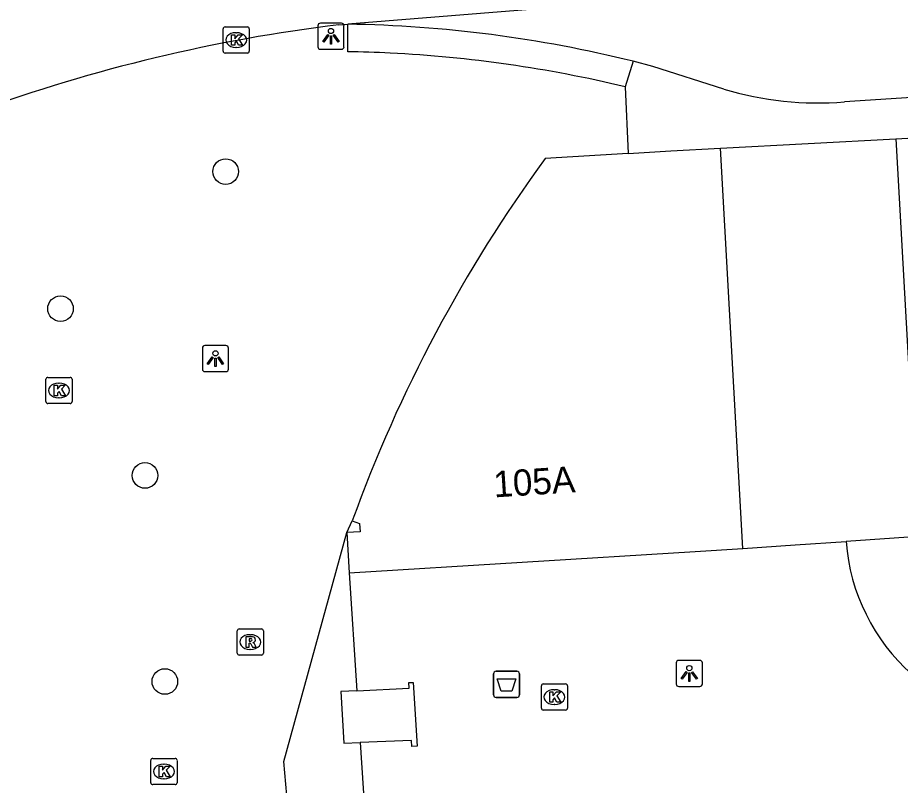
# Model space of a CAD drawing. Extents: x 159689 to 160786, y 387323 to 388339.
# Drawn here: x 160232.81 to 160266.51, y 387796.36 to 387825.64 of the extents above; entities that cross this region are included whole.
import ezdxf

# ---------------------------------------------------------------- set-up
doc = ezdxf.new("R2010")
doc.units = 0
for name, color, linetype in [('IMGEO_Afvalbak', 7, 'Continuous'), ('IMGEO_Boom', 7, 'Continuous'), ('IMGEO_Kolk', 7, 'Continuous'), ('IMGEO_Lichtpunt', 7, 'Continuous'), ('IMGEO_Pand', 7, 'Continuous'), ('IMGEO_Pand_nummerreeks', 7, 'Continuous'), ('IMGEO_Rijbaan_lokaal_open', 7, 'Continuous'), ('IMGEO_Rioolput', 7, 'Continuous'), ('IMGEO_Voetpad_open', 7, 'Continuous')]:
    doc.layers.add(name, color=color, linetype=linetype)

msp = doc.modelspace()

# ---------------------------------------------------------------- linework, layer by layer
at = {"layer": 'IMGEO_Afvalbak'}
for p, q in [((160250.976, 387799.808), (160250.976, 387800.608)), ((160250.976, 387800.608), (160250.976, 387799.808)), ((160251.076, 387800.708), (160251.866, 387800.708)), ((160251.866, 387800.708), (160251.076, 387800.708)), ((160251.966, 387800.608), (160251.966, 387799.808)), ((160251.966, 387799.808), (160251.966, 387800.608)), ((160251.866, 387799.708), (160251.076, 387799.708)), ((160251.076, 387799.708), (160251.866, 387799.708))]:
    msp.add_line(p, q, dxfattribs=at)
msp.add_lwpolyline([(160251.119, 387800.422), (160251.823, 387800.422), (160251.674, 387799.952), (160251.268, 387799.952), (160251.119, 387800.422)], dxfattribs=at)
for centre, start, end in [((160251.076, 387800.608), 90, 180), ((160251.076, 387800.608), 90, 180), ((160251.866, 387800.608), 0, 90), ((160251.866, 387800.608), 360, 90), ((160251.076, 387799.808), 180, 270), ((160251.076, 387799.808), 180, 270), ((160251.866, 387799.808), 270, 0), ((160251.866, 387799.808), 270, 0)]:
    msp.add_arc(centre, 0.1, start, end, dxfattribs=at)
at = {"layer": 'IMGEO_Boom'}
for centre in [(160240.754, 387819.771), (160234.448, 387814.541), (160237.673, 387808.179), (160238.431, 387800.318)]:
    msp.add_circle(centre, 0.489, dxfattribs=at)
at = {"layer": 'IMGEO_Kolk'}
for p, q in [((160240.654, 387824.364), (160240.654, 387825.216)), ((160240.729, 387825.29), (160241.581, 387825.29)), ((160241.142, 387825.07), (160241.167, 387825.07)), ((160241.655, 387825.216), (160241.655, 387824.364)), ((160241.165, 387824.51), (160241.14, 387824.51)), ((160241.581, 387824.29), (160240.729, 387824.29)), ((160233.963, 387811.921), (160234.815, 387811.921)), ((160233.888, 387810.995), (160233.888, 387811.847)), ((160234.376, 387811.701), (160234.401, 387811.701)), ((160234.889, 387811.847), (160234.889, 387810.995)), ((160234.815, 387810.921), (160233.963, 387810.921)), ((160234.399, 387811.141), (160234.374, 387811.141)), ((160252.802, 387799.3), (160252.802, 387800.152)), ((160252.877, 387800.226), (160253.729, 387800.226)), ((160253.803, 387800.152), (160253.803, 387799.3)), ((160253.29, 387800.006), (160253.315, 387800.006)), ((160253.313, 387799.446), (160253.288, 387799.446)), ((160253.729, 387799.226), (160252.877, 387799.226)), ((160237.895, 387796.459), (160237.895, 387797.311)), ((160237.97, 387797.385), (160238.822, 387797.385)), ((160238.383, 387797.165), (160238.408, 387797.165)), ((160238.896, 387797.311), (160238.896, 387796.459)), ((160238.822, 387796.385), (160237.97, 387796.385)), ((160238.406, 387796.605), (160238.381, 387796.605))]:
    msp.add_line(p, q, dxfattribs=at)
for points in [[(160240.654, 387824.364), (160240.654, 387825.216)], [(160240.729, 387825.29), (160241.581, 387825.29)], [(160241.655, 387825.216), (160241.655, 387824.364)], [(160240.975, 387824.99), (160241.098, 387824.99), (160241.098, 387824.839), (160241.228, 387824.99), (160241.392, 387824.99), (160241.246, 387824.839), (160241.399, 387824.59), (160241.247, 387824.59), (160241.162, 387824.754), (160241.098, 387824.687), (160241.098, 387824.59), (160240.975, 387824.59), (160240.975, 387824.99)], [(160241.581, 387824.29), (160240.729, 387824.29)], [(160233.963, 387811.921), (160234.815, 387811.921)], [(160233.888, 387810.995), (160233.888, 387811.847)], [(160234.209, 387811.621), (160234.332, 387811.621), (160234.332, 387811.47), (160234.462, 387811.621), (160234.626, 387811.621), (160234.48, 387811.47), (160234.633, 387811.221), (160234.481, 387811.221), (160234.396, 387811.385), (160234.332, 387811.318), (160234.332, 387811.221), (160234.209, 387811.221), (160234.209, 387811.621)], [(160234.889, 387811.847), (160234.889, 387810.995)], [(160234.815, 387810.921), (160233.963, 387810.921)], [(160252.802, 387799.3), (160252.802, 387800.152)], [(160252.877, 387800.226), (160253.729, 387800.226)], [(160253.803, 387800.152), (160253.803, 387799.3)], [(160253.123, 387799.926), (160253.246, 387799.926), (160253.246, 387799.775), (160253.376, 387799.926), (160253.54, 387799.926), (160253.394, 387799.775), (160253.547, 387799.526), (160253.395, 387799.526), (160253.31, 387799.69), (160253.246, 387799.623), (160253.246, 387799.526), (160253.123, 387799.526), (160253.123, 387799.926)], [(160253.729, 387799.226), (160252.877, 387799.226)], [(160237.895, 387796.459), (160237.895, 387797.311)], [(160237.97, 387797.385), (160238.822, 387797.385)], [(160238.216, 387797.085), (160238.339, 387797.085), (160238.339, 387796.934), (160238.469, 387797.085), (160238.633, 387797.085), (160238.487, 387796.934), (160238.64, 387796.685), (160238.488, 387796.685), (160238.403, 387796.849), (160238.339, 387796.782), (160238.339, 387796.685), (160238.216, 387796.685), (160238.216, 387797.085)], [(160238.896, 387797.311), (160238.896, 387796.459)], [(160238.822, 387796.385), (160237.97, 387796.385)]]:
    msp.add_lwpolyline(points, dxfattribs=at)
for centre, start, end in [((160240.731, 387825.214), 91.552, 178.448), ((160240.731, 387825.214), 91.552, 178.448), ((160241.579, 387825.214), 1.552, 88.448), ((160241.579, 387825.214), 1.552, 88.448), ((160240.731, 387824.366), 181.552, 268.448), ((160240.731, 387824.366), 181.552, 268.448), ((160241.579, 387824.366), 271.552, 358.448), ((160241.579, 387824.366), 271.552, 358.448), ((160233.965, 387811.845), 91.552, 178.448), ((160233.965, 387811.845), 91.552, 178.448), ((160234.813, 387811.845), 1.552, 88.448), ((160234.813, 387811.845), 1.552, 88.448), ((160233.965, 387810.997), 181.552, 268.448), ((160233.965, 387810.997), 181.552, 268.448), ((160234.813, 387810.997), 271.552, 358.448), ((160234.813, 387810.997), 271.552, 358.448), ((160252.879, 387800.15), 91.552, 178.448), ((160252.879, 387800.15), 91.552, 178.448), ((160253.727, 387800.15), 1.552, 88.448), ((160253.727, 387800.15), 1.552, 88.448), ((160252.879, 387799.302), 181.552, 268.448), ((160252.879, 387799.302), 181.552, 268.448), ((160253.727, 387799.302), 271.552, 358.448), ((160253.727, 387799.302), 271.552, 358.448), ((160237.972, 387797.309), 91.552, 178.448), ((160237.972, 387797.309), 91.552, 178.448), ((160238.82, 387797.309), 1.552, 88.448), ((160238.82, 387797.309), 1.552, 88.448), ((160237.972, 387796.461), 181.552, 268.448), ((160237.972, 387796.461), 181.552, 268.448), ((160238.82, 387796.461), 271.552, 358.448), ((160238.82, 387796.461), 271.552, 358.448)]:
    msp.add_arc(centre, 0.0765, start, end, dxfattribs=at)
for centre, major_axis, ratio, start_param, end_param in [((160241.141, 387824.79), (-0.387, 0.002), 0.722429, 4.712389, 7.853982), ((160241.166, 387824.79), (-0.39, 0.002), 0.717154, 1.570796, 4.712389), ((160234.375, 387811.421), (-0.387, 0.002), 0.722429, 4.712389, 7.853982), ((160234.4, 387811.421), (-0.39, 0.002), 0.717154, 1.570796, 4.712389), ((160253.289, 387799.726), (-0.387, 0.002), 0.722429, 4.712389, 7.853982), ((160253.314, 387799.726), (-0.39, 0.002), 0.717154, 1.570796, 4.712389), ((160238.382, 387796.885), (-0.387, 0.002), 0.722429, 4.712389, 7.853982), ((160238.407, 387796.885), (-0.39, 0.002), 0.717154, 1.570796, 4.712389)]:
    msp.add_ellipse(centre, major_axis=major_axis, ratio=ratio, start_param=start_param, end_param=end_param, dxfattribs=at)
at = {"layer": 'IMGEO_Lichtpunt'}
for p, q in [((160245.175, 387825.432), (160244.367, 387825.432)), ((160245.175, 387825.432), (160244.367, 387825.432)), ((160244.273, 387825.337), (160244.273, 387824.53)), ((160244.273, 387825.337), (160244.273, 387824.53)), ((160245.269, 387824.53), (160245.269, 387825.337)), ((160245.269, 387824.53), (160245.269, 387825.337)), ((160244.367, 387824.436), (160245.175, 387824.436)), ((160244.367, 387824.436), (160245.175, 387824.436)), ((160239.863, 387813.04), (160239.863, 387812.233)), ((160239.863, 387813.04), (160239.863, 387812.233)), ((160240.765, 387813.135), (160239.957, 387813.135)), ((160240.765, 387813.135), (160239.957, 387813.135)), ((160240.859, 387812.233), (160240.859, 387813.04)), ((160240.859, 387812.233), (160240.859, 387813.04)), ((160239.957, 387812.139), (160240.765, 387812.139)), ((160239.957, 387812.139), (160240.765, 387812.139)), ((160258.854, 387801.125), (160258.046, 387801.125)), ((160258.854, 387801.125), (160258.046, 387801.125)), ((160257.952, 387801.03), (160257.952, 387800.223)), ((160257.952, 387801.03), (160257.952, 387800.223)), ((160258.948, 387800.223), (160258.948, 387801.03)), ((160258.948, 387800.223), (160258.948, 387801.03)), ((160258.046, 387800.129), (160258.854, 387800.129)), ((160258.046, 387800.129), (160258.854, 387800.129))]:
    msp.add_line(p, q, dxfattribs=at)
for points in [[(160244.647, 387825.001), (160244.686, 387824.973), (160244.498, 387824.711), (160244.46, 387824.738), (160244.647, 387825.001)], [(160244.749, 387824.953), (160244.796, 387824.953), (160244.796, 387824.631), (160244.749, 387824.631), (160244.749, 387824.953)], [(160244.859, 387824.973), (160244.897, 387825), (160245.084, 387824.738), (160245.045, 387824.71), (160244.859, 387824.973)], [(160240.237, 387812.704), (160240.276, 387812.676), (160240.088, 387812.414), (160240.05, 387812.441), (160240.237, 387812.704)], [(160240.339, 387812.656), (160240.386, 387812.656), (160240.386, 387812.334), (160240.339, 387812.334), (160240.339, 387812.656)], [(160240.449, 387812.676), (160240.487, 387812.703), (160240.674, 387812.441), (160240.635, 387812.413), (160240.449, 387812.676)], [(160258.326, 387800.694), (160258.365, 387800.666), (160258.177, 387800.404), (160258.139, 387800.431), (160258.326, 387800.694)], [(160258.428, 387800.646), (160258.475, 387800.646), (160258.475, 387800.324), (160258.428, 387800.324), (160258.428, 387800.646)], [(160258.538, 387800.666), (160258.576, 387800.693), (160258.763, 387800.431), (160258.724, 387800.403), (160258.538, 387800.666)]]:
    msp.add_lwpolyline(points, dxfattribs=at)
for centre in [(160244.772, 387825.135), (160240.362, 387812.838), (160258.451, 387800.828)]:
    msp.add_circle(centre, 0.0994, dxfattribs=at)
for centre, start, end in [((160244.367, 387825.337), 90, 180), ((160244.367, 387825.337), 90, 180), ((160245.175, 387825.337), 0, 90), ((160245.175, 387825.337), 0, 90), ((160244.367, 387824.53), 180, 270), ((160244.367, 387824.53), 180, 270), ((160245.175, 387824.53), 270, 0), ((160245.175, 387824.53), 270, 360), ((160239.957, 387813.04), 90, 180), ((160239.957, 387813.04), 90, 180), ((160240.765, 387813.04), 0, 90), ((160240.765, 387813.04), 0, 90), ((160239.957, 387812.233), 180, 270), ((160239.957, 387812.233), 180, 270), ((160240.765, 387812.233), 270, 0), ((160240.765, 387812.233), 270, 360), ((160258.046, 387801.03), 90, 180), ((160258.046, 387801.03), 90, 180), ((160258.854, 387801.03), 0, 90), ((160258.854, 387801.03), 0, 90), ((160258.046, 387800.223), 180, 270), ((160258.046, 387800.223), 180, 270), ((160258.854, 387800.223), 270, 0), ((160258.854, 387800.223), 270, 360)]:
    msp.add_arc(centre, 0.0946, start, end, dxfattribs=at)
at = {"layer": 'IMGEO_Pand'}
for points in [[(160266.337, 387821.024), (160273.033, 387821.388), (160273.123, 387820.044), (160312.863, 387822.702)], [(160259.64, 387820.661), (160266.337, 387821.024)], [(160266.337, 387821.024), (160267.186, 387805.852), (160264.435, 387805.656)], [(160256.117, 387820.458), (160257.749, 387820.558), (160259.64, 387820.661)], [(160260.493, 387805.395), (160259.64, 387820.661)], [(160256.117, 387820.458), (160252.945, 387820.264)], [(160245.584, 387806.446), (160245.858, 387806.345), (160245.886, 387806.024), (160245.383, 387805.999)], [(160245.383, 387805.999), (160245.468, 387804.459)], [(160260.493, 387805.395), (160262.485, 387805.527), (160264.435, 387805.656)], [(160245.468, 387804.459), (160258.676, 387805.274), (160260.493, 387805.395)], [(160245.763, 387799.965), (160247.757, 387800.059), (160247.747, 387800.278), (160247.912, 387800.285), (160248.061, 387797.847), (160247.861, 387797.838), (160247.851, 387798.063), (160245.892, 387797.991)], [(160245.763, 387799.965), (160245.151, 387799.936), (160245.269, 387797.968), (160245.892, 387797.991)]]:
    msp.add_lwpolyline(points, dxfattribs=at)
for centre, radius, start, end in [((160297.69, 387787.558), 55.424, 143.8356, 160.075), ((160271.923, 387806.22), 7.51, 184.3083, 228.486)]:
    msp.add_arc(centre, radius, start, end, dxfattribs=at)
at = {"layer": 'IMGEO_Rijbaan_lokaal_open'}
for points in [[(160267.095, 387827.148), (160245.41, 387825.395)], [(160245.077, 387825.369), (160245.41, 387825.395)], [(160325.4, 387824.392), (160307.674, 387823.303), (160280.899, 387821.601), (160274.521, 387821.163), (160274.439, 387822.446), (160274.398, 387823.082), (160266.548, 387822.576), (160264.374, 387822.431)], [(160259.765, 387822.918), (160257.054, 387823.783), (160256.303, 387823.982)]]:
    msp.add_lwpolyline(points, dxfattribs=at)
for centre, radius, start, end in [((160252.477, 387763.928), 61.885, 96.86731, 110.06178), ((160244.598, 387776.444), 48.957, 76.168, 89.0502), ((160263.35, 387834.793), 12.405, 253.2015, 274.7351)]:
    msp.add_arc(centre, radius, start, end, dxfattribs=at)
at = {"layer": 'IMGEO_Rioolput'}
for p, q in [((160241.191, 387801.398), (160241.191, 387802.25)), ((160241.266, 387802.324), (160242.118, 387802.324)), ((160242.192, 387802.25), (160242.192, 387801.398)), ((160241.679, 387802.104), (160241.704, 387802.104)), ((160241.702, 387801.544), (160241.677, 387801.544)), ((160242.118, 387801.324), (160241.266, 387801.324))]:
    msp.add_line(p, q, dxfattribs=at)
for points in [[(160241.191, 387801.398), (160241.191, 387802.25)], [(160241.266, 387802.324), (160242.118, 387802.324)], [(160242.192, 387802.25), (160242.192, 387801.398)], [(160241.78, 387802.022), (160241.528, 387802.024), (160241.528, 387801.624)], [(160241.528, 387801.624), (160241.652, 387801.624), (160241.652, 387801.786), (160241.663, 387801.786)], [(160241.706, 387801.943), (160241.652, 387801.943), (160241.652, 387801.862)], [(160241.652, 387801.862), (160241.704, 387801.862)], [(160241.71, 387801.757), (160241.781, 387801.624), (160241.921, 387801.624), (160241.856, 387801.75)], [(160242.118, 387801.324), (160241.266, 387801.324)]]:
    msp.add_lwpolyline(points, dxfattribs=at)
for centre, radius, start, end in [((160241.268, 387802.248), 0.0765, 91.552, 178.448), ((160241.268, 387802.248), 0.0765, 91.552, 178.448), ((160242.116, 387802.248), 0.0765, 1.552, 88.448), ((160242.116, 387802.248), 0.0765, 1.552, 88.448), ((160241.662, 387801.733), 0.0533, 26.0293, 88.6989), ((160241.688, 387802.051), 0.19, 274.7715, 282.9687), ((160241.712, 387801.847), 0.0964, 77.0061, 93.1865), ((160241.726, 387801.904), 0.0378, 276.6634, 79.6772), ((160241.779, 387801.912), 0.109, 350.3612, 89.416), ((160241.777, 387801.912), 0.112, 277.5842, 350.9817), ((160241.761, 387801.697), 0.108, 29.5134, 73.7905), ((160241.268, 387801.4), 0.0765, 181.552, 268.448), ((160241.268, 387801.4), 0.0765, 181.552, 268.448), ((160242.116, 387801.4), 0.0765, 271.552, 358.448), ((160242.116, 387801.4), 0.0765, 271.552, 358.448)]:
    msp.add_arc(centre, radius, start, end, dxfattribs=at)
for centre, major_axis, ratio, start_param, end_param in [((160241.678, 387801.824), (-0.387, 0.002), 0.722429, 4.712389, 7.853982), ((160241.703, 387801.824), (-0.39, 0.002), 0.717154, 1.570796, 4.712389)]:
    msp.add_ellipse(centre, major_axis=major_axis, ratio=ratio, start_param=start_param, end_param=end_param, dxfattribs=at)
at = {"layer": 'IMGEO_Voetpad_open'}
for points in [[(160245.41, 387824.345), (160245.41, 387825.395)], [(160256.303, 387823.982), (160256, 387823.006)], [(160256, 387823.006), (160256.117, 387820.458)], [(160245.383, 387805.999), (160245.584, 387806.446)], [(160243.165, 387795.102), (160242.978, 387797.27), (160245.383, 387805.999)], [(160245.468, 387804.459), (160245.763, 387799.965)], [(160245.892, 387797.991), (160246.07, 387795.277)]]:
    msp.add_lwpolyline(points, dxfattribs=at)
for centre, radius, start, end in [((160244.659, 387777.459), 46.892, 87.1011, 89.0829), ((160244.586, 387775.285), 49.067, 76.549, 87.1443)]:
    msp.add_arc(centre, radius, start, end, dxfattribs=at)

# ---------------------------------------------------------------- texts
at = {"layer": 'IMGEO_Pand_nummerreeks'}
msp.add_text('105A', height=1, rotation=3.6727, dxfattribs=at).set_placement((160251.005, 387807.34))

doc.saveas('drawing.dxf')
